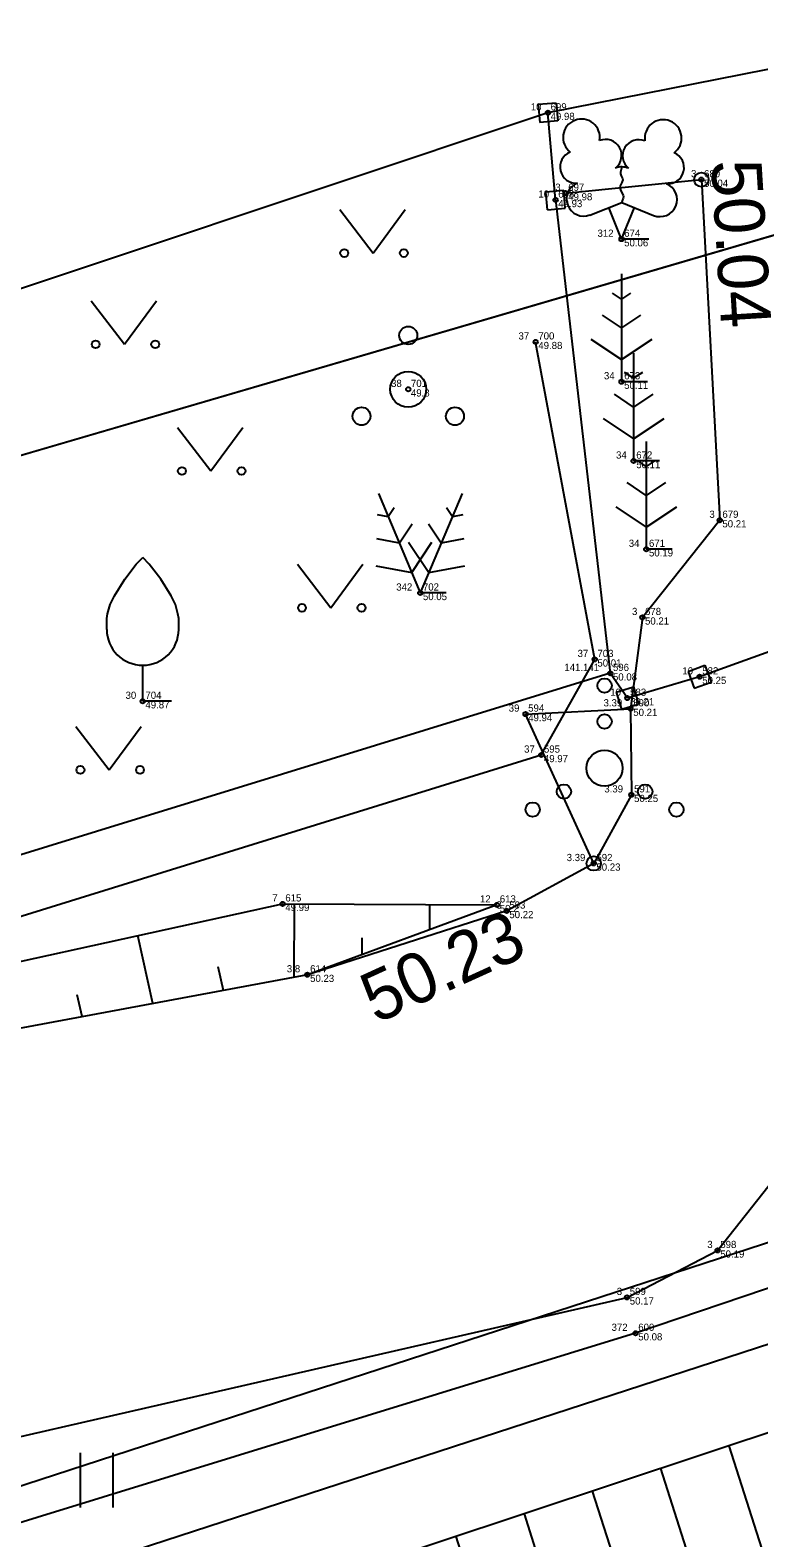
# Model space of a CAD drawing. Extents: x 543497 to 552146, y 6567125 to 6579845.
# Drawn here: x 546052.53 to 546062.67, y 6577696.47 to 6577717.44 of the extents above; entities that cross this region are included whole.
import ezdxf

# ---------------------------------------------------------------- set-up
doc = ezdxf.new("R2010")
doc.units = 0
for name, color, linetype in [('xref_Kangru tee 1_geodeesia$0$AED', 7, 'Continuous'), ('xref_Kangru tee 1_geodeesia$0$HALJASTUS', 7, 'Continuous'), ('xref_Kangru tee 1_geodeesia$0$korgus-EH2000', 7, 'Continuous'), ('xref_Kangru tee 1_geodeesia$0$mootkood', 7, 'Continuous'), ('xref_Kangru tee 1_geodeesia$0$MOOTKORG-eh2000', 7, 'Continuous'), ('xref_Kangru tee 1_geodeesia$0$mootmpunkt', 7, 'Continuous'), ('xref_Kangru tee 1_geodeesia$0$MOOTNR', 7, 'Continuous'), ('xref_Kangru tee 1_geodeesia$0$MOOTPIIR', 7, 'Continuous'), ('xref_Kangru tee 1_geodeesia$0$PIIR', 7, 'Continuous'), ('xref_Kangru tee 1_geodeesia$0$PUU', 7, 'Continuous'), ('xref_Kangru tee 1_geodeesia$0$RELJEEF', 7, 'Continuous'), ('xref_Kangru tee 1_geodeesia$0$SITRASS', 7, 'Continuous'), ('xref_Kangru tee 1_geodeesia$0$TEE', 7, 'Continuous')]:
    doc.layers.add(name, color=color, linetype=linetype)

# ---------------------------------------------------------------- blocks, each defined once
blk = doc.blocks.new('xref_Kangru tee 1_geodeesia$0$varpos')
for p, q in [((-0.25, 0.25), (-0.25, -0.25)), ((-0.25, 0.25), (0.25, 0.25)), ((0.25, 0.25), (0.25, -0.25)), ((-0.25, -0.25), (0.25, -0.25))]:
    blk.add_line(p, q)
blk = doc.blocks.new('xref_Kangru tee 1_geodeesia$0$mand1')
for p, q in [((0, 3), (0, 0)), ((0, 2.3), (-0.249, 2.466)), ((0.249, 2.466), (0, 2.3)), ((0, 1.5), (-0.533, 1.855)), ((0.533, 1.855), (0, 1.5)), ((-0.849, 1.179), (0, 0.613)), ((0, 0.613), (0.849, 1.179)), ((0.72, 0), (0, 0))]:
    blk.add_line(p, q)
blk = doc.blocks.new('xref_Kangru tee 1_geodeesia$0$LEHTP2')
for p, q in [((-0.88, 0.67), (0.01, 1.02)), ((0, 0), (-0.35, 0.88)), ((0, 0), (0.36, 0.88)), ((0.01, 1.02), (0.89, 0.66)), ((0.76, 0), (0, 0))]:
    blk.add_line(p, q)
blk.add_lwpolyline([(0.01, 2.01), (-0.03, 1.86), (-0.03, 1.82), (-0.01, 1.76), (0.03, 1.69), (0.04, 1.65), (0.01, 1.58), (-0.04, 1.48), (-0.05, 1.43), (-0.04, 1.4), (-0.02, 1.34), (0.05, 1.22), (0.06, 1.18), (0.05, 1.14), (0.02, 1.07), (0.01, 1.02)])
for centre, radius, start, end in [((-1.114, 2.828), 0.512, 111.5027, 232.5173), ((-1.114, 2.828), 0.512, 350.4856, 111.5002), ((1.158, 2.811), 0.512, 67.6168, 188.6314), ((1.158, 2.811), 0.512, 306.5997, 67.6143), ((-0.445, 2.327), 0.448, 308.5041, 111.5725), ((0.481, 2.318), 0.45, 67.7016, 230.5126), ((-1.262, 2.005), 0.448, 111.4304, 274.4987), ((1.293, 1.986), 0.448, 264.6183, 67.6866), ((0.008, 1.535), 0.475, 66.7655, 111.5015), ((-1.053, 1.117), 0.475, 111.5014, 291.5004), ((1.07, 1.101), 0.475, 247.6166, 67.6155)]:
    blk.add_arc(centre, radius, start, end)
blk = doc.blocks.new('xref_Kangru tee 1_geodeesia$0$PQQSAS')
for centre, radius in [((0, 1.5), 0.25), ((0, 0), 0.5), ((-1.3, -0.75), 0.25), ((1.3, -0.75), 0.25)]:
    blk.add_circle(centre, radius)
blk = doc.blocks.new('xref_Kangru tee 1_geodeesia$0$MAND2')
for p, q in [((-1.165, 2.765), (0, 0)), ((1.165, 2.765), (0, 0)), ((-0.893, 2.12), (-1.187, 2.176)), ((-0.728, 2.369), (-0.893, 2.12)), ((0.893, 2.12), (0.728, 2.369)), ((1.187, 2.176), (0.893, 2.12)), ((-0.229, 1.917), (-0.582, 1.382)), ((0.582, 1.382), (0.229, 1.917)), ((-0.582, 1.382), (-1.212, 1.503)), ((-0.324, 1.416), (0.238, 0.565)), ((-0.238, 0.565), (0.324, 1.416)), ((1.212, 1.503), (0.582, 1.382)), ((-1.24, 0.757), (-0.238, 0.565)), ((0.238, 0.565), (1.24, 0.757)), ((0.72, 0), (0, 0))]:
    blk.add_line(p, q)
blk = doc.blocks.new('xref_Kangru tee 1_geodeesia$0$VILJA1')
for p, q in [((0, 0), (0, 1)), ((0.8, 0), (0, 0))]:
    blk.add_line(p, q)
for points in [[(-1, 2), (-1, 2.3), (-0.98, 2.43), (-0.91, 2.69), (-0.79, 2.93), (-0.5, 3.4), (-0.18, 3.81), (0, 4)], [(1, 2), (1, 2.3), (0.98, 2.43), (0.91, 2.69), (0.79, 2.93), (0.5, 3.4), (0.18, 3.81), (0, 4)]]:
    blk.add_lwpolyline(points)
blk.add_arc((0, 2), 1, 180, 0)
blk = doc.blocks.new('xref_Kangru tee 1_geodeesia$0$VQSA')
for centre, radius in [((0, 2.3), 0.2), ((0, 1.3), 0.2), ((0, 0), 0.5), ((-1.13, -0.65), 0.2), ((1.13, -0.65), 0.2), ((-2, -1.15), 0.2), ((2, -1.15), 0.2)]:
    blk.add_circle(centre, radius)
blk = doc.blocks.new('xref_Kangru tee 1_geodeesia$0$hein')
for p, q in [((-0.455, 0.761), (-0.455, -0.761)), ((0.455, 0.761), (0.455, -0.761))]:
    blk.add_line(p, q)
blk = doc.blocks.new('xref_Kangru tee 1_geodeesia$0$MURU')
for p, q in [((-0.927, 1.213), (0, 0)), ((0, 0), (0.891, 1.213))]:
    blk.add_line(p, q)
for centre in [(-0.802, 0), (0.856, 0)]:
    blk.add_circle(centre, 0.11)

msp = doc.modelspace()

# ---------------------------------------------------------------- linework, layer by layer
at = {"layer": 'xref_Kangru tee 1_geodeesia$0$AED'}
for points in [[(545979.768, 6577672.182), (545997.507, 6577677.911), (546020.844, 6577685.508), (546045.969, 6577693.685), (546068.657, 6577701.074), (546085.99, 6577706.708), (546091.783, 6577708.468), (546114.483, 6577715.305), (546122.781, 6577717.859)], [(546059.838, 6577715.079), (546059.732, 6577716.292)], [(546059.838, 6577715.079), (546060.599, 6577708.494), (546043.656, 6577703.273), (546024.552, 6577697.712), (546024.121, 6577700.643), (546019.535, 6577705.044)], [(546067.53, 6577710.494), (546061.841, 6577708.446)], [(546060.838, 6577708.149), (546060.599, 6577708.494)], [(546061.841, 6577708.446), (546060.838, 6577708.149)]]:
    msp.add_lwpolyline(points, dxfattribs=at)
at = {"layer": 'xref_Kangru tee 1_geodeesia$0$HALJASTUS'}
for points in [[(546028.276, 6577697.987), (546044.001, 6577702.512), (546059.639, 6577707.358), (546060.383, 6577708.688), (546059.561, 6577713.105)], [(546060.369, 6577705.849), (546059.42, 6577707.928), (546060.882, 6577708.001)]]:
    msp.add_lwpolyline(points, dxfattribs=at)
at = {"layer": 'xref_Kangru tee 1_geodeesia$0$korgus-EH2000'}
for centre in [(546061.866, 6577715.362), (546060.369, 6577705.849)]:
    msp.add_circle(centre, 0.1, dxfattribs=at)
at = {"layer": 'xref_Kangru tee 1_geodeesia$0$mootmpunkt'}
for centre in [(546059.732, 6577716.292), (546061.866, 6577715.362), (546059.977, 6577715.174), (546059.838, 6577715.079), (546060.755, 6577714.534), (546059.561, 6577713.105), (546057.789, 6577712.445), (546060.755, 6577712.551), (546060.923, 6577711.448), (546062.121, 6577710.624), (546061.1, 6577710.22), (546057.956, 6577709.612), (546061.045, 6577709.272), (546060.383, 6577708.688), (546060.599, 6577708.494), (546061.841, 6577708.446), (546054.096, 6577708.106), (546060.838, 6577708.149), (546060.882, 6577708.001), (546059.42, 6577707.928), (546059.639, 6577707.358), (546060.893, 6577706.804), (546060.369, 6577705.849), (546056.042, 6577705.287), (546059.025, 6577705.273), (546059.158, 6577705.188), (546056.387, 6577704.301), (546062.092, 6577700.466), (546060.833, 6577699.813), (546060.951, 6577699.314)]:
    msp.add_circle(centre, 0.03, dxfattribs=at)
at = {"layer": 'xref_Kangru tee 1_geodeesia$0$MOOTPIIR'}
msp.add_lwpolyline([(546091.362, 6577730.835), (546076.174, 6577727.357), (546069.665, 6577722.185), (546069.859, 6577718.295), (546059.732, 6577716.292), (546047.281, 6577712.138), (546039.381, 6577710.647), (546032.006, 6577709.907), (546022.782, 6577705.611), (546019.535, 6577705.044), (546019.82, 6577703.764), (546018.234, 6577702.863), (546014.32, 6577701.586), (545991.87, 6577693.345), (545969.52, 6577687.243)], dxfattribs=at)
at = {"layer": 'xref_Kangru tee 1_geodeesia$0$PIIR'}
for points in [[(545983.53, 6577775.51), (546081.11, 6577806.12), (546096.86, 6577764.18), (546079.41, 6577756.98), (546054.12, 6577754.83), (546055.48, 6577740.79), (546080.65, 6577742.83), (546099.69, 6577747.34), (546110.26, 6577728.46), (545969.55, 6577687.28), (545983.53, 6577775.51)], [(545526.72, 6577483.94), (545567.61, 6577503.92), (545600.27, 6577519.26), (545639.76, 6577537.43), (545673.8, 6577552.72), (545712.72, 6577569.73), (545743.83, 6577582.87), (545764.02, 6577591.24), (545805.47, 6577607.21), (545907.89, 6577644.25), (545925.88, 6577650.4), (545918.84, 6577672.45), (545921.7, 6577673.29), (545969.55, 6577687.28), (546110.26, 6577728.46), (546113.86, 6577718.6), (546117.94, 6577707.48), (546328.8, 6577761.79)]]:
    msp.add_lwpolyline(points, dxfattribs=at)
at = {"layer": 'xref_Kangru tee 1_geodeesia$0$PUU'}
msp.add_lwpolyline([(546117.866, 6577717.426), (546113.699, 6577716.286), (546090.767, 6577709.285), (546067.25, 6577701.449), (546060.951, 6577699.314), (546047.057, 6577695.034), (546019.897, 6577686.031), (545997.772, 6577678.867)], dxfattribs=at)
at = {"layer": 'xref_Kangru tee 1_geodeesia$0$RELJEEF'}
for p, q in [((546056.202, 6577704.267), (546056.206, 6577705.286)), ((546058.087, 6577704.927), (546058.088, 6577705.277)), ((546054.235, 6577703.901), (546054.028, 6577704.845)), ((546057.148, 6577704.582), (546057.149, 6577704.815)), ((546055.218, 6577704.084), (546055.147, 6577704.409)), ((546053.252, 6577703.718), (546053.185, 6577704.022)), ((546062.246, 6577697.749), (546063.313, 6577694.409)), ((546061.297, 6577697.433), (546061.652, 6577696.324)), ((546060.348, 6577697.118), (546061.408, 6577693.8)), ((546059.399, 6577696.803), (546059.751, 6577695.7)), ((546058.45, 6577696.488), (546059.503, 6577693.191))]:
    msp.add_line(p, q, dxfattribs=at)
for points in [[(546137.781, 6577720.873), (546114.77, 6577714.002), (546092.255, 6577707.342), (546069.036, 6577700.004), (546046.331, 6577692.462), (546021.153, 6577684.174), (545998.132, 6577676.3), (545981.547, 6577670.953), (545979.653, 6577670.251), (545977.742, 6577668.092), (545973.561, 6577666.634), (545951.988, 6577659.65), (545928.335, 6577650.688), (545904.994, 6577641.739)], [(546040.274, 6577700.368), (546044.989, 6577702.414), (546049.957, 6577703.951), (546056.042, 6577705.287), (546059.025, 6577705.273)], [(546059.025, 6577705.273), (546056.387, 6577704.301)]]:
    msp.add_lwpolyline(points, dxfattribs=at)
at = {"layer": 'xref_Kangru tee 1_geodeesia$0$SITRASS'}
msp.add_lwpolyline([(545908.485, 6577643.705), (545911.194, 6577646.612), (545925.706, 6577656.002), (545927.481, 6577656.734), (545938.042, 6577659.913), (545948.418, 6577663.054), (545958.853, 6577666.457), (545971.932, 6577670.246), (545983.129, 6577674.156), (545994.132, 6577677.914), (546005.032, 6577681.831), (546015.499, 6577685.452), (546025.557, 6577688.556), (546030.559, 6577690.213), (546046.952, 6577695.414), (546066.518, 6577701.793), (546078.972, 6577705.852), (546100.203, 6577712.621), (546110.553, 6577715.537), (546117.41, 6577717.31), (546125.411, 6577719.428), (546136.464, 6577722.314), (546141.561, 6577723.784)], dxfattribs=at)
at = {"layer": 'xref_Kangru tee 1_geodeesia$0$TEE'}
for points in [[(545971.433, 6577672.366), (545997.276, 6577680.49), (546019.075, 6577687.637), (546046.227, 6577696.261), (546050.233, 6577697.38), (546060.833, 6577699.813), (546062.092, 6577700.466), (546063.421, 6577702.15), (546066.8, 6577702.917), (546090.631, 6577711.146), (546112.837, 6577718.304), (546121.35, 6577721.07), (546120.4, 6577725.737), (546111.41, 6577723.208), (546088.914, 6577715.843), (546065.816, 6577706.486), (546065.244, 6577706.703), (546065.037, 6577707.357), (546065.171, 6577709.425), (546065.38, 6577710.653), (546064.96, 6577714.947), (546067.921, 6577716.792), (546070.994, 6577716.678), (546072.733, 6577718.476)], [(546059.977, 6577715.174), (546061.866, 6577715.362), (546062.121, 6577710.624), (546061.045, 6577709.272), (546060.882, 6577708.001), (546060.893, 6577706.804), (546060.369, 6577705.849), (546059.158, 6577705.188), (546056.387, 6577704.301), (546050.232, 6577703.156), (546045.314, 6577701.613), (546044.543, 6577701.325), (546040.274, 6577700.368), (546017.855, 6577692.963), (545995.651, 6577685.598), (545969.99, 6577676.752), (545949.859, 6577670.253), (545932.117, 6577664.712), (545929.387, 6577664.046), (545924.424, 6577663.904), (545920.826, 6577664.534), (545918.964, 6577665.384), (545916.564, 6577667.08), (545914.824, 6577669.08)]]:
    msp.add_lwpolyline(points, dxfattribs=at)

# ---------------------------------------------------------------- block references
at = {"layer": 'xref_Kangru tee 1_geodeesia$0$AED'}
for p, xscale, yscale, rotation in [((546059.732, 6577716.292), 0.5, 0.5, -85.0058008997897), ((546059.838, 6577715.079), 0.49999999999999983, 0.4999999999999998, 94.99419910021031), ((546061.841, 6577708.446), 0.5, 0.5, 19.79851971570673), ((546060.838, 6577708.149), 0.5, 0.5, 16.494636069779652)]:
    msp.add_blockref('xref_Kangru tee 1_geodeesia$0$varpos', p, dxfattribs=dict(at, xscale=xscale, yscale=yscale, rotation=rotation))
at = {"layer": 'xref_Kangru tee 1_geodeesia$0$HALJASTUS', "xscale": 0.5, "yscale": 0.5}
for name, p in [('xref_Kangru tee 1_geodeesia$0$MURU', (546057.3, 6577714.34)), ('xref_Kangru tee 1_geodeesia$0$MURU', (546053.842, 6577713.071)), ('xref_Kangru tee 1_geodeesia$0$MURU', (546055.042, 6577711.309)), ('xref_Kangru tee 1_geodeesia$0$MURU', (546056.712, 6577709.405)), ('xref_Kangru tee 1_geodeesia$0$VQSA', (546060.519, 6577707.174)), ('xref_Kangru tee 1_geodeesia$0$MURU', (546053.63, 6577707.15)), ('xref_Kangru tee 1_geodeesia$0$hein', (546053.452, 6577697.269))]:
    msp.add_blockref(name, p, dxfattribs=at)
at = {"layer": 'xref_Kangru tee 1_geodeesia$0$PUU', "xscale": 0.5, "yscale": 0.5}
for name, p in [('xref_Kangru tee 1_geodeesia$0$LEHTP2', (546060.755, 6577714.534)), ('xref_Kangru tee 1_geodeesia$0$mand1', (546060.755, 6577712.551)), ('xref_Kangru tee 1_geodeesia$0$PQQSAS', (546057.789, 6577712.445)), ('xref_Kangru tee 1_geodeesia$0$mand1', (546060.923, 6577711.448)), ('xref_Kangru tee 1_geodeesia$0$mand1', (546061.1, 6577710.22)), ('xref_Kangru tee 1_geodeesia$0$MAND2', (546057.956, 6577709.612)), ('xref_Kangru tee 1_geodeesia$0$VILJA1', (546054.096, 6577708.106))]:
    msp.add_blockref(name, p, dxfattribs=at)

# ---------------------------------------------------------------- texts
at = {"layer": 'xref_Kangru tee 1_geodeesia$0$korgus-EH2000'}
for s, rotation, p in [(' 50.04 ', 273.4942, (546061.985, 6577715.88)), (' 50.23 ', 24.4629, (546057.104, 6577703.506))]:
    msp.add_text(s, height=0.7, rotation=rotation, dxfattribs=at).set_placement(p)
at = {"layer": 'xref_Kangru tee 1_geodeesia$0$mootkood'}
for s, p in [(' 10', (546059.456, 6577716.325)), (' 3', (546061.685, 6577715.395)), (' 10', (546059.562, 6577715.112)), (' 3', (546059.796, 6577715.207)), (' 312', (546060.384, 6577714.567)), (' 37', (546059.285, 6577713.138)), (' 34', (546060.474, 6577712.584)), (' 38', (546057.513, 6577712.478)), (' 34', (546060.642, 6577711.481)), (' 3', (546061.94, 6577710.657)), (' 34', (546060.819, 6577710.253)), (' 342', (546057.585, 6577709.645)), (' 3', (546060.864, 6577709.305)), (' 37', (546060.107, 6577708.721)), (' 141.141', (546059.923, 6577708.527)), (' 10', (546061.565, 6577708.479)), (' 30', (546053.82, 6577708.139)), (' 10', (546060.562, 6577708.182)), (' 39', (546059.149, 6577707.961)), (' 3.39', (546060.468, 6577708.034)), (' 37', (546059.363, 6577707.391)), (' 3.39', (546060.479, 6577706.837)), (' 3.39', (546059.955, 6577705.882)), (' 7', (546055.861, 6577705.32)), (' 12', (546058.749, 6577705.306)), (' 3', (546058.977, 6577705.221)), (' 3.8', (546056.063, 6577704.334)), (' 3', (546061.911, 6577700.499)), (' 3', (546060.652, 6577699.846)), (' 372', (546060.58, 6577699.347))]:
    msp.add_text(s, height=0.1, dxfattribs=at).set_placement(p)
at = {"layer": 'xref_Kangru tee 1_geodeesia$0$MOOTKORG-eh2000'}
for s, p in [(' 49.98', (546059.732, 6577716.192)), (' 49.98', (546059.977, 6577715.074)), (' 50.04', (546061.866, 6577715.262)), (' 49.93', (546059.838, 6577714.979)), (' 50.06', (546060.755, 6577714.434)), (' 49.88', (546059.561, 6577713.005)), (' 49.8', (546057.789, 6577712.345)), (' 50.11', (546060.755, 6577712.451)), (' 50.11', (546060.923, 6577711.348)), (' 50.21', (546062.121, 6577710.524)), (' 50.19', (546061.1, 6577710.12)), (' 50.05', (546057.956, 6577709.512)), (' 50.21', (546061.045, 6577709.172)), (' 50.01', (546060.383, 6577708.588)), (' 50.08', (546060.599, 6577708.394)), (' 50.25', (546061.841, 6577708.346)), (' 49.87', (546054.096, 6577708.006)), (' 50.21', (546060.838, 6577708.049)), (' 49.94', (546059.42, 6577707.828)), (' 50.21', (546060.882, 6577707.901)), (' 49.97', (546059.639, 6577707.258)), (' 50.25', (546060.893, 6577706.704)), (' 50.23', (546060.369, 6577705.749)), (' 49.99', (546056.042, 6577705.187)), (' 50.2', (546059.025, 6577705.173)), (' 50.22', (546059.158, 6577705.088)), (' 50.23', (546056.387, 6577704.201)), (' 50.19', (546062.092, 6577700.366)), (' 50.17', (546060.833, 6577699.713)), (' 50.08', (546060.951, 6577699.214))]:
    msp.add_text(s, height=0.1, dxfattribs=at).set_placement(p)
at = {"layer": 'xref_Kangru tee 1_geodeesia$0$MOOTNR'}
for s, p in [(' 699', (546059.732, 6577716.325)), (' 680', (546061.866, 6577715.395)), (' 698', (546059.838, 6577715.112)), (' 697', (546059.977, 6577715.207)), (' 674', (546060.755, 6577714.567)), (' 700', (546059.561, 6577713.138)), (' 673', (546060.755, 6577712.584)), (' 701', (546057.789, 6577712.478)), (' 672', (546060.923, 6577711.481)), (' 679', (546062.121, 6577710.657)), (' 671', (546061.1, 6577710.253)), (' 702', (546057.956, 6577709.645)), (' 678', (546061.045, 6577709.305)), (' 703', (546060.383, 6577708.721)), (' 596', (546060.599, 6577708.527)), (' 582', (546061.841, 6577708.479)), (' 704', (546054.096, 6577708.139)), (' 583', (546060.838, 6577708.182)), (' 594', (546059.42, 6577707.961)), (' 590', (546060.882, 6577708.034)), (' 595', (546059.639, 6577707.391)), (' 591', (546060.893, 6577706.837)), (' 592', (546060.369, 6577705.882)), (' 615', (546056.042, 6577705.32)), (' 613', (546059.025, 6577705.306)), (' 593', (546059.158, 6577705.221)), (' 614', (546056.387, 6577704.334)), (' 598', (546062.092, 6577700.499)), (' 599', (546060.833, 6577699.846)), (' 600', (546060.951, 6577699.347))]:
    msp.add_text(s, height=0.1, dxfattribs=at).set_placement(p)

doc.saveas('drawing.dxf')
